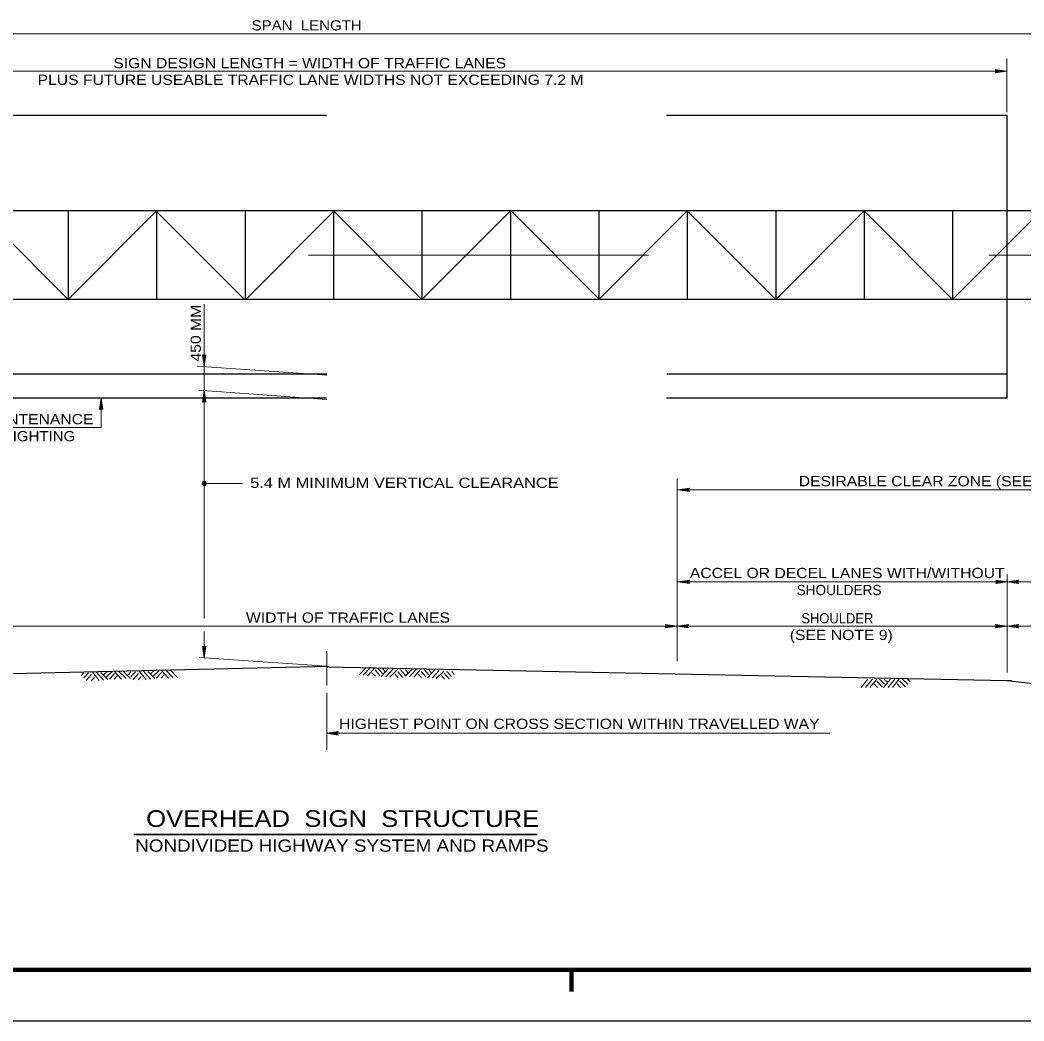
# Model space of a CAD drawing. Extents: x 312601.858 to 312602.699, y 144420.127 to 144420.721.
# Drawn here: x 312602.1162 to 312602.4113, y 144420.1268 to 144420.4208 of the extents above; entities that cross this region are included whole.
import ezdxf
from ezdxf.enums import TextEntityAlignment as Align

# ---------------------------------------------------------------- set-up
doc = ezdxf.new("R2010")
doc.units = 0
doc.header["$LTSCALE"] = 0.0012
doc.linetypes.add('DOT_DASHED', pattern=[7.7, 5, -1.2, 0.3, -1.2])
doc.linetypes.add('LONG_DASHED', pattern=[7.5, 6, -1.5])
for name, color, linetype, lineweight in [('1', 7, 'Continuous', 13), ('2', 7, 'Continuous', 13), ('39', 7, 'Continuous', 13)]:
    doc.layers.add(name, color=color, linetype=linetype, lineweight=lineweight)

msp = doc.modelspace()

# ---------------------------------------------------------------- hatches: boundary and pattern name
at = {"layer": '39'}
for points in [[(312602.4031, 144420.4058), (312602.4028, 144420.4063), (312602.4062, 144420.4058), (312602.4028, 144420.4053)], [(312602.1703, 144420.3222), (312602.1708, 144420.3225), (312602.1703, 144420.3191), (312602.1698, 144420.3225)], [(312602.1703, 144420.3089), (312602.1698, 144420.3086), (312602.1703, 144420.312), (312602.1708, 144420.3086)], [(312602.14, 144420.3067), (312602.1395, 144420.3064), (312602.14, 144420.3098), (312602.1405, 144420.3064)], [(312602.1709, 144420.2847, 1), (312602.1697, 144420.2847, 1)], [(312602.3126, 144420.2828), (312602.3129, 144420.2823), (312602.3095, 144420.2828), (312602.3129, 144420.2833)], [(312602.3126, 144420.2828), (312602.3129, 144420.2823), (312602.3095, 144420.2828), (312602.3129, 144420.2833)], [(312602.3126, 144420.2558), (312602.3129, 144420.2553), (312602.3095, 144420.2558), (312602.3129, 144420.2563)], [(312602.3126, 144420.2558), (312602.3129, 144420.2553), (312602.3095, 144420.2558), (312602.3129, 144420.2563)], [(312602.4033, 144420.2558), (312602.403, 144420.2563), (312602.4064, 144420.2558), (312602.403, 144420.2553)], [(312602.4033, 144420.2558), (312602.403, 144420.2563), (312602.4064, 144420.2558), (312602.403, 144420.2553)], [(312602.4094, 144420.2558), (312602.4097, 144420.2553), (312602.4063, 144420.2558), (312602.4097, 144420.2563)], [(312602.3062, 144420.2428), (312602.3059, 144420.2433), (312602.3093, 144420.2428), (312602.3059, 144420.2423)], [(312602.3124, 144420.2428), (312602.3127, 144420.2423), (312602.3093, 144420.2428), (312602.3127, 144420.2433)], [(312602.4032, 144420.2428), (312602.4029, 144420.2433), (312602.4063, 144420.2428), (312602.4029, 144420.2423)], [(312602.4032, 144420.2428), (312602.4029, 144420.2433), (312602.4063, 144420.2428), (312602.4029, 144420.2423)], [(312602.4094, 144420.2428), (312602.4097, 144420.2423), (312602.4063, 144420.2428), (312602.4097, 144420.2433)], [(312602.4094, 144420.2428), (312602.4097, 144420.2423), (312602.4063, 144420.2428), (312602.4097, 144420.2433)], [(312602.1703, 144420.2366), (312602.1708, 144420.2369), (312602.1703, 144420.2335), (312602.1698, 144420.2369)], [(312602.1703, 144420.2366), (312602.1708, 144420.2369), (312602.1703, 144420.2335), (312602.1698, 144420.2369)], [(312602.2094, 144420.2113), (312602.2097, 144420.2108), (312602.2063, 144420.2113), (312602.2097, 144420.2118)]]:
    msp.add_hatch(color=256, dxfattribs=at).paths.add_polyline_path(points)

# ---------------------------------------------------------------- linework, layer by layer
at = {"layer": '1'}
for p, q in [((312602.1394, 144420.2268), (312602.1374, 144420.2293)), ((312602.1407, 144420.2269), (312602.1386, 144420.2293)), ((312602.142, 144420.2271), (312602.1399, 144420.2292)), ((312602.1417, 144420.2294), (312602.1408, 144420.2286)), ((312602.1431, 144420.2294), (312602.1416, 144420.2279)), ((312602.146, 144420.2272), (312602.1439, 144420.2295)), ((312602.1473, 144420.2274), (312602.1451, 144420.2296)), ((312602.1486, 144420.2274), (312602.1465, 144420.2296)), ((312602.1487, 144420.2294), (312602.1479, 144420.2285)), ((312602.1501, 144420.2294), (312602.1487, 144420.2279)), ((312602.1532, 144420.2271), (312602.1512, 144420.2296)), ((312602.1545, 144420.2272), (312602.1524, 144420.2296)), ((312602.1558, 144420.2274), (312602.1537, 144420.2295)), ((312602.1555, 144420.2297), (312602.1546, 144420.2289)), ((312602.1569, 144420.2297), (312602.1554, 144420.2282)), ((312602.1577, 144420.2292), (312602.1562, 144420.2275)), ((312602.1598, 144420.2275), (312602.1577, 144420.2298)), ((312602.1611, 144420.2277), (312602.1589, 144420.2299)), ((312602.1624, 144420.2277), (312602.1603, 144420.2299)), ((312602.2158, 144420.2285), (312602.2179, 144420.2306)), ((312602.217, 144420.2284), (312602.2192, 144420.2306)), ((312602.2183, 144420.2282), (312602.2204, 144420.2305)), ((312602.2205, 144420.2299), (312602.2219, 144420.2282)), ((312602.2213, 144420.2304), (312602.2227, 144420.2289)), ((312602.2223, 144420.228), (312602.2245, 144420.2303)), ((312602.2227, 144420.2304), (312602.2234, 144420.2295)), ((312602.2237, 144420.2279), (312602.2258, 144420.2302)), ((312602.2249, 144420.2278), (312602.2271, 144420.23)), ((312602.2272, 144420.2294), (312602.2287, 144420.2277)), ((312602.228, 144420.2299), (312602.2294, 144420.2284)), ((312602.2294, 144420.2281), (312602.2315, 144420.2302)), ((312602.2295, 144420.2299), (312602.2302, 144420.229)), ((312602.2306, 144420.228), (312602.2328, 144420.2302)), ((312602.2319, 144420.2278), (312602.234, 144420.2301)), ((312602.2341, 144420.2295), (312602.2355, 144420.2278)), ((312602.2349, 144420.23), (312602.2363, 144420.2285)), ((312602.2359, 144420.2276), (312602.2381, 144420.2299)), ((312602.2363, 144420.23), (312602.237, 144420.2291)), ((312602.2373, 144420.2275), (312602.2394, 144420.2298)), ((312602.2385, 144420.2274), (312602.2407, 144420.2296)), ((312602.2416, 144420.2295), (312602.243, 144420.228)), ((312602.2431, 144420.2295), (312602.2438, 144420.2286)), ((312602.1349, 144420.2291), (312602.1341, 144420.2282)), ((312602.1363, 144420.2291), (312602.1349, 144420.2276)), ((312602.1372, 144420.2286), (312602.1356, 144420.2268)), ((312602.138, 144420.2277), (312602.1371, 144420.2267)), ((312602.1439, 144420.2289), (312602.1424, 144420.2272)), ((312602.1447, 144420.2282), (312602.1438, 144420.2272)), ((312602.151, 144420.2289), (312602.1494, 144420.2271)), ((312602.1518, 144420.228), (312602.1509, 144420.227)), ((312602.1585, 144420.2285), (312602.1576, 144420.2275)), ((312602.2196, 144420.2291), (312602.2206, 144420.2281)), ((312602.2264, 144420.2287), (312602.2273, 144420.2276)), ((312602.2332, 144420.2287), (312602.2342, 144420.2277)), ((312602.24, 144420.2283), (312602.2409, 144420.2272)), ((312602.2408, 144420.229), (312602.2423, 144420.2273)), ((312602.3634, 144420.2248), (312602.3654, 144420.2272)), ((312602.3647, 144420.2248), (312602.3667, 144420.2272)), ((312602.366, 144420.2248), (312602.368, 144420.2272)), ((312602.368, 144420.2266), (312602.3696, 144420.225)), ((312602.3688, 144420.2272), (312602.3703, 144420.2257)), ((312602.37, 144420.2248), (312602.372, 144420.2272)), ((312602.3702, 144420.2272), (312602.371, 144420.2264)), ((312602.3713, 144420.2248), (312602.3733, 144420.2272)), ((312602.3726, 144420.2248), (312602.3746, 144420.2272)), ((312602.3748, 144420.2266), (312602.3764, 144420.225)), ((312602.3756, 144420.2272), (312602.3771, 144420.2257)), ((312602.377, 144420.2272), (312602.3778, 144420.2264)), ((312602.3672, 144420.2258), (312602.3682, 144420.2248)), ((312602.374, 144420.2258), (312602.375, 144420.2248))]:
    msp.add_line(p, q, dxfattribs=at)
at = {"layer": '2'}
msp.add_lwpolyline([(312602.064, 144420.3011), (312602.14, 144420.3011), (312602.14, 144420.3098)], dxfattribs=at)
at = {"layer": '39'}
for p, q in [((312602.4718, 144420.4168), (312601.9448, 144420.4168)), ((312602.4062, 144420.4096), (312602.4062, 144420.3938)), ((312602.4062, 144420.4058), (312602.0217, 144420.4058)), ((312602.1303, 144420.3388), (312602.1563, 144420.3648)), ((312602.1303, 144420.3388), (312602.1563, 144420.3648)), ((312602.1303, 144420.3388), (312602.1563, 144420.3648)), ((312602.2343, 144420.3388), (312602.2083, 144420.3648)), ((312602.2343, 144420.3388), (312602.2083, 144420.3648)), ((312602.2063, 144420.3165), (312602.1682, 144420.3192)), ((312602.2063, 144420.3094), (312602.1686, 144420.3121)), ((312602.1703, 144420.312), (312602.1703, 144420.245)), ((312602.3093, 144420.2862), (312602.3093, 144420.2325)), ((312602.1703, 144420.2847), (312602.1815, 144420.2847)), ((312602.3095, 144420.2828), (312602.4693, 144420.2828)), ((312602.4063, 144420.258), (312602.4063, 144420.2292)), ((312602.1703, 144420.2412), (312602.1703, 144420.2335)), ((312602.4063, 144420.2428), (312602.4442, 144420.2428)), ((312602.2063, 144420.231), (312602.1688, 144420.2336)), ((312602.4053, 144420.2268), (312602.4076, 144420.2268)), ((312602.2063, 144420.2232), (312602.2063, 144420.2063)), ((312602.2063, 144420.2113), (312602.3542, 144420.2113))]:
    msp.add_line(p, q, dxfattribs=at)
at = {"layer": '39', "linetype": 'LONG_DASHED', "lineweight": 25}
for p, q in [((312602.4062, 144420.3928), (312602.0218, 144420.3928)), ((312602.4062, 144420.3929), (312602.4062, 144420.3098)), ((312602.4063, 144420.3168), (312602.0218, 144420.3168)), ((312602.4062, 144420.3098), (312602.0218, 144420.3098))]:
    msp.add_line(p, q, dxfattribs=at)
at = {"layer": '39', "lineweight": 25}
for p, q in [((312602.475, 144420.3648), (312601.9956, 144420.3648)), ((312602.1303, 144420.3388), (312602.1043, 144420.3648)), ((312602.1303, 144420.3648), (312602.1303, 144420.3388)), ((312602.1303, 144420.3388), (312602.1563, 144420.3648)), ((312602.1821, 144420.3388), (312602.1561, 144420.3648)), ((312602.1563, 144420.3648), (312602.1563, 144420.3388)), ((312602.1823, 144420.3648), (312602.1823, 144420.3388)), ((312602.1825, 144420.3388), (312602.2085, 144420.3648)), ((312602.2083, 144420.3648), (312602.2083, 144420.3388)), ((312602.2343, 144420.3388), (312602.2083, 144420.3648)), ((312602.2343, 144420.3648), (312602.2343, 144420.3388)), ((312602.2343, 144420.3388), (312602.2603, 144420.3648)), ((312602.2603, 144420.3648), (312602.2603, 144420.3388)), ((312602.2865, 144420.3388), (312602.2605, 144420.3648)), ((312602.2863, 144420.3648), (312602.2863, 144420.3388)), ((312602.2863, 144420.3388), (312602.3123, 144420.3648)), ((312602.3123, 144420.3648), (312602.3123, 144420.3388)), ((312602.3383, 144420.3388), (312602.3123, 144420.3648)), ((312602.3383, 144420.3648), (312602.3383, 144420.3388)), ((312602.3383, 144420.3388), (312602.3643, 144420.3648)), ((312602.3643, 144420.3648), (312602.3643, 144420.3388)), ((312602.3903, 144420.3388), (312602.3643, 144420.3648)), ((312602.3903, 144420.3648), (312602.3903, 144420.3388)), ((312602.3903, 144420.3388), (312602.4163, 144420.3648)), ((312602.4756, 144420.3388), (312601.9952, 144420.3388)), ((312602.0217, 144420.2268), (312602.207, 144420.231)), ((312602.2063, 144420.2308), (312602.4063, 144420.2268)), ((312601.8578, 144420.1268), (312602.6988, 144420.1268))]:
    msp.add_line(p, q, dxfattribs=at)
at = {"layer": '39', "linetype": 'DOT_DASHED'}
for p, q in [((312602.0009, 144420.3518), (312602.4896, 144420.3518)), ((312602.2063, 144420.2354), (312602.2063, 144420.2253))]:
    msp.add_line(p, q, dxfattribs=at)
at = {"layer": '39', "lineweight": 35}
msp.add_line((312602.1496, 144420.1816), (312602.2682, 144420.1816), dxfattribs=at)
at = {"layer": '39', "lineweight": 158}
for p, q in [((312601.9088, 144420.1418), (312602.6838, 144420.1418)), ((312602.2783, 144420.1354), (312602.2783, 144420.1418))]:
    msp.add_line(p, q, dxfattribs=at)
at = {"layer": '39'}
for points in [[(312602.4031, 144420.4058), (312602.4028, 144420.4063), (312602.4062, 144420.4058), (312602.4028, 144420.4053)], [(312602.1703, 144420.3222), (312602.1708, 144420.3225), (312602.1703, 144420.3191), (312602.1698, 144420.3225)], [(312602.1703, 144420.3089), (312602.1698, 144420.3086), (312602.1703, 144420.312), (312602.1708, 144420.3086)], [(312602.14, 144420.3067), (312602.1395, 144420.3064), (312602.14, 144420.3098), (312602.1405, 144420.3064)], [(312602.3126, 144420.2828), (312602.3129, 144420.2823), (312602.3095, 144420.2828), (312602.3129, 144420.2833)], [(312602.3126, 144420.2828), (312602.3129, 144420.2823), (312602.3095, 144420.2828), (312602.3129, 144420.2833)], [(312602.3126, 144420.2558), (312602.3129, 144420.2553), (312602.3095, 144420.2558), (312602.3129, 144420.2563)], [(312602.3126, 144420.2558), (312602.3129, 144420.2553), (312602.3095, 144420.2558), (312602.3129, 144420.2563)], [(312602.4033, 144420.2558), (312602.403, 144420.2563), (312602.4064, 144420.2558), (312602.403, 144420.2553)], [(312602.4033, 144420.2558), (312602.403, 144420.2563), (312602.4064, 144420.2558), (312602.403, 144420.2553)], [(312602.4094, 144420.2558), (312602.4097, 144420.2553), (312602.4063, 144420.2558), (312602.4097, 144420.2563)], [(312602.3062, 144420.2428), (312602.3059, 144420.2433), (312602.3093, 144420.2428), (312602.3059, 144420.2423)], [(312602.3124, 144420.2428), (312602.3127, 144420.2423), (312602.3093, 144420.2428), (312602.3127, 144420.2433)], [(312602.4032, 144420.2428), (312602.4029, 144420.2433), (312602.4063, 144420.2428), (312602.4029, 144420.2423)], [(312602.4032, 144420.2428), (312602.4029, 144420.2433), (312602.4063, 144420.2428), (312602.4029, 144420.2423)], [(312602.4094, 144420.2428), (312602.4097, 144420.2423), (312602.4063, 144420.2428), (312602.4097, 144420.2433)], [(312602.4094, 144420.2428), (312602.4097, 144420.2423), (312602.4063, 144420.2428), (312602.4097, 144420.2433)], [(312602.1703, 144420.2366), (312602.1708, 144420.2369), (312602.1703, 144420.2335), (312602.1698, 144420.2369)], [(312602.1703, 144420.2366), (312602.1708, 144420.2369), (312602.1703, 144420.2335), (312602.1698, 144420.2369)], [(312602.2094, 144420.2113), (312602.2097, 144420.2108), (312602.2063, 144420.2113), (312602.2097, 144420.2118)]]:
    msp.add_lwpolyline(points, close=True, dxfattribs=at)
for points in [[(312602.1703, 144420.3374), (312602.1703, 144420.3191), (312602.1703, 144420.312)], [(312602.3095, 144420.2558), (312602.4063, 144420.2558), (312602.4693, 144420.2558)], [(312602.0218, 144420.2428), (312602.1033, 144420.2428), (312602.1703, 144420.2428), (312602.3093, 144420.2428), (312602.4063, 144420.2428)]]:
    msp.add_lwpolyline(points, dxfattribs=at)
at = {"layer": '39', "lineweight": 25}
msp.add_lwpolyline([(312602.4063, 144420.2268), (312602.4718, 144420.2193), (312602.5, 144420.2175)], dxfattribs=at)
at = {"layer": '39'}
msp.add_circle((312602.1703, 144420.2847), 0.0006, dxfattribs=at)

# ---------------------------------------------------------------- texts
at = {"layer": '2', "width": 1.15}
msp.add_text('450 MM', height=0.003, rotation=90, dxfattribs=at).set_placement((312602.1693, 144420.32885), align=Align.CENTER)
at = {"layer": '2'}
for s, width, p in [('LOWER LIMIT OF MAINTENANCE', 1.15, (312602.0652, 144420.3021)), ('WALKWAY AND SIGN LIGHTING', 1.1, (312602.0652, 144420.2971))]:
    msp.add_text(s, height=0.003, dxfattribs=dict(at, width=width)).set_placement(p)
at = {"layer": '39'}
for s, height, width, p in [('SPAN  LENGTH', 0.003, 1.1, (312602.2004, 144420.4178)), ('SIGN DESIGN LENGTH = WIDTH OF TRAFFIC LANES', 0.003, 1.15, (312602.2013, 144420.4067)), ('PLUS FUTURE USEABLE TRAFFIC LANE WIDTHS NOT EXCEEDING 7.2 M', 0.003, 1.15, (312602.20155, 144420.4018)), ('5.4 M MINIMUM VERTICAL CLEARANCE ', 0.003, 1.2, (312602.2298, 144420.2834)), ('DESIRABLE CLEAR ZONE (SEE NOTE 8) ', 0.003, 1.15, (312602.3898, 144420.2839)), ('ACCEL OR DECEL LANES WITH/WITHOUT ', 0.003, 1.15, (312602.35995, 144420.2569)), ('WIDTH OF TRAFFIC LANES', 0.003, 1.15, (312602.21255, 144420.2438)), ('SHOULDER', 0.003, 0.95, (312602.3564, 144420.2436)), ('(SEE NOTE 9) ', 0.003, 1.15, (312602.3582, 144420.2387)), ('HIGHEST POINT ON CROSS SECTION WITHIN TRAVELLED WAY', 0.003, 1.15, (312602.28055, 144420.2126)), ('OVERHEAD  SIGN  STRUCTURE', 0.0049, 1.15, (312602.211, 144420.1838)), ('NONDIVIDED HIGHWAY SYSTEM AND RAMPS', 0.0036, 1.15, (312602.21075, 144420.1765))]:
    msp.add_text(s, height=height, dxfattribs=dict(at, width=width)).set_placement(p, align=Align.CENTER)
msp.add_text('SHOULDERS', height=0.003, dxfattribs=at).set_placement((312602.3569, 144420.2519), align=Align.CENTER)

doc.saveas('drawing.dxf')
